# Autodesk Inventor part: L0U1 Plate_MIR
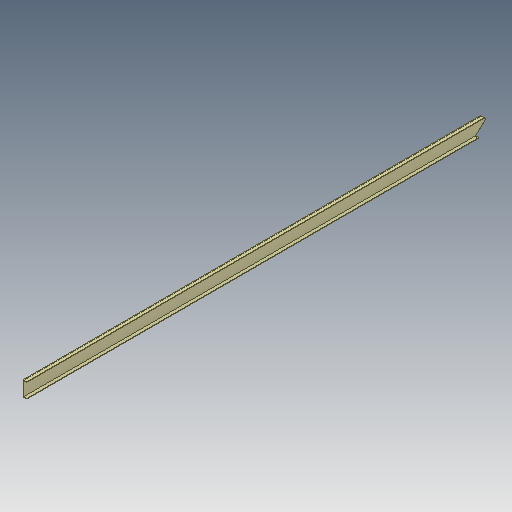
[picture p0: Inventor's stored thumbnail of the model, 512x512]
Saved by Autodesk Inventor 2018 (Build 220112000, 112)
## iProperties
Created: 2018-02
Part Number: L0U1 Plate_MIR
Material: Steel, Mild
Document SubType Name: Modeling
Designer: STK
Density: 7.85 g/cm^3
Appearance: Semi-Polished
Author: STK
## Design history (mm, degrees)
derived "L0U1 Plate.ipt"
  sketch "Sketch1"
    geometry: L1 (-12.7, 177.8)-(-12.7, -177.8) reference; L2 (0, -190.5)-(0, 190.5) reference; L3 (0, -190.5)-(-92.075, -190.5) reference; L4 (-92.075, -190.5)-(-92.075, -177.8) reference; L5 (-92.075, -177.8)-(-12.7, -177.8) reference; L6 (0, 190.5)-(-92.075, 190.5) reference; L7 (-92.075, 190.5)-(-92.075, 177.8) reference; L8 (-92.075, 177.8)-(-12.7, 177.8) reference; L9 (0, 0)-(-92.075, 0) reference
  sketch "Sketch3"
    geometry: L1 (-5208.737, -5473.469)-(136.194, 252.93) reference; L2 (136.194, 252.93)-(407.176, 0) reference; L3 (11887.2, 0)-(0, 0) reference; L4 (136.194, 252.93)-(255.733, 381) reference; L5 (11887.2, 381)-(0, 381) reference; L6 (255.733, 381)-(0, 381) reference; L7 (0, 381)-(0, 0) reference; L8 (0, 0)-(407.176, 0) reference; 1 further point
  sketch "Sketch4"
    geometry: L1 (0, 0)-(-408.192, 381) reference; L2 (270.982, -252.93)-(7.543, -7.041) reference; L3 (0, 381)-(-11631.467, 381) reference; L4 (0, 381)-(0, 0) reference; L5 (0, 381)-(-408.192, 381) reference; 1 further point
feature "Solid1::L0U1 Plate.ipt"
tag "TaggingFeature1"
body "Solid1"
